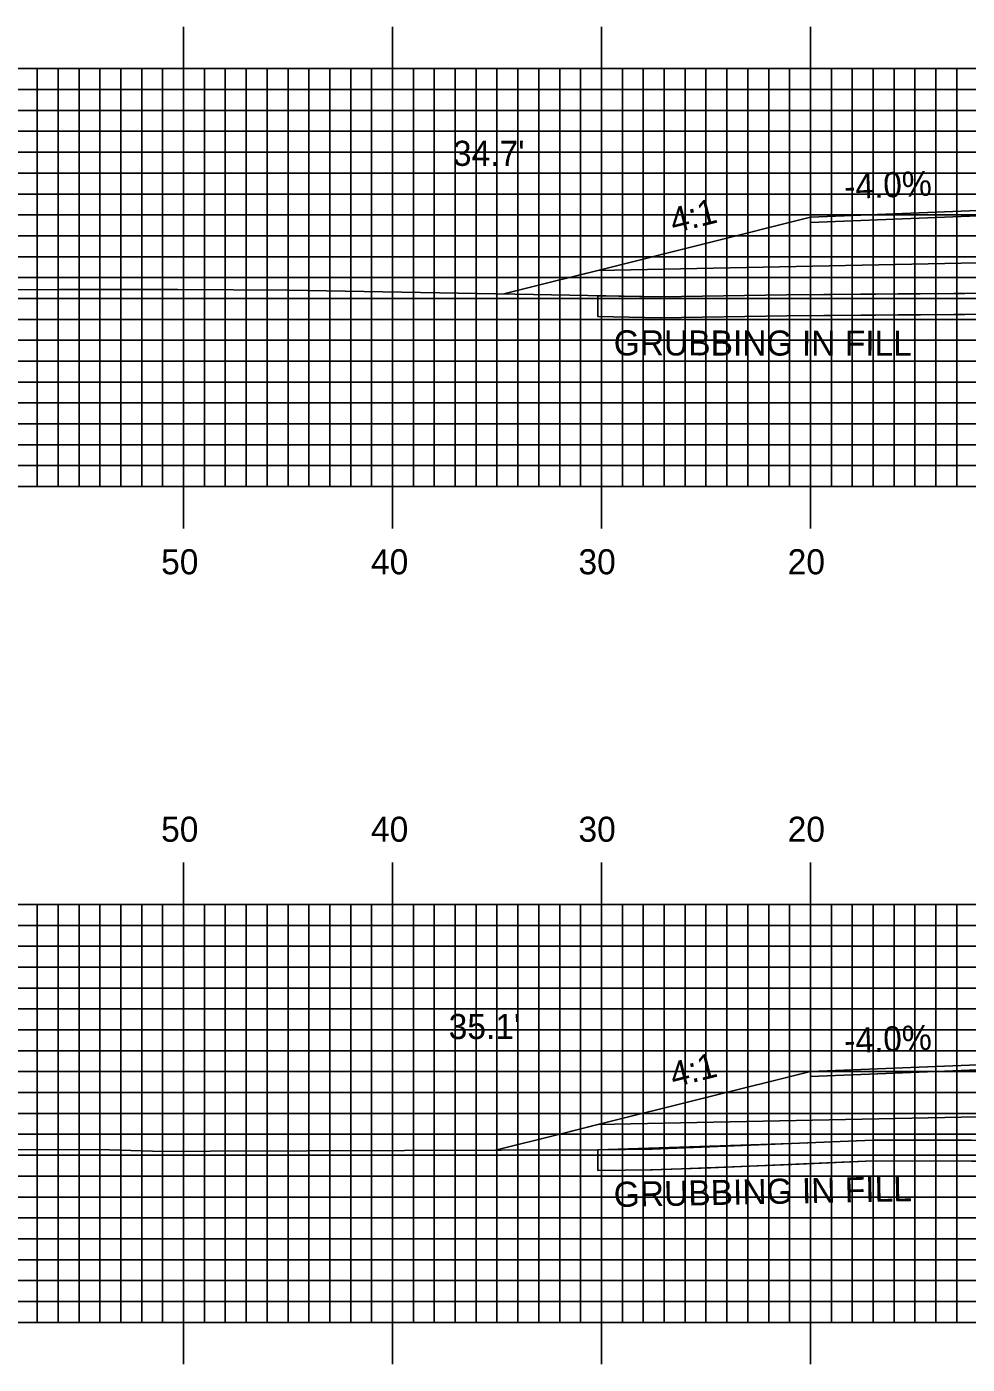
# Model space of a CAD drawing. Extents: x 1778712 to 1779055, y 442591 to 442811.
# Drawn here: x 1778820.3 to 1778865.3, y 442686.7 to 442750.7 of the extents above; entities that cross this region are included whole.
import ezdxf

# ---------------------------------------------------------------- set-up
doc = ezdxf.new("R2010")
doc.units = 0
for name, color, linetype in [('ANNOTATION', 7, 'Continuous'), ('D_Roadway_Centerline', 7, 'Continuous'), ('D_Roadway_Edge_Shoulder', 7, 'Continuous'), ('D_Roadway_SlopeLines', 7, 'Continuous'), ('D_Roadway_SubGrade', 7, 'Continuous'), ('D_Text_Standard', 7, 'Continuous'), ('GRUBBING IN FILL', 7, 'Continuous'), ('H_V ANNOTATION', 7, 'Continuous'), ('MAJOR', 7, 'Continuous'), ('MINOR', 7, 'Continuous'), ('S_Roadway_Centerline', 7, 'Continuous')]:
    doc.layers.add(name, color=color, linetype=linetype)

msp = doc.modelspace()

# ---------------------------------------------------------------- linework, layer by layer
at = {"layer": 'D_Roadway_Centerline'}
for points in [[(1778843.141, 442737.884), (1778845.246, 442738.41), (1778845.816, 442738.552), (1778846.159, 442738.638), (1778847.642, 442739.009), (1778857.816, 442741.552), (1778860.631, 442741.665), (1778865.816, 442741.872), (1778871.523, 442741.986), (1778877.816, 442742.112), (1778889.816, 442741.872), (1778909.797, 442741.073)], [(1778842.737, 442696.908), (1778845.816, 442697.677), (1778847.142, 442698.009), (1778847.643, 442698.134), (1778857.816, 442700.677), (1778865.816, 442700.997), (1778866.485, 442701.011), (1778877.816, 442701.237), (1778882.23, 442701.149), (1778889.816, 442700.997), (1778896.708, 442700.722), (1778908.134, 442700.264), (1778917.409, 442697.946)]]:
    msp.add_lwpolyline(points, dxfattribs=at)
at = {"layer": 'D_Roadway_Edge_Shoulder'}
for points in [[(1778865.816, 442741.872), (1778857.816, 442741.552), (1778857.816, 442741.302), (1778865.816, 442741.622)], [(1778865.816, 442700.997), (1778857.816, 442700.677), (1778857.816, 442700.427), (1778865.816, 442700.747)]]:
    msp.add_lwpolyline(points, close=True, dxfattribs=at)
at = {"layer": 'D_Roadway_SlopeLines'}
for points in [[(1778857.816, 442741.552), (1778847.642, 442739.009), (1778845.816, 442738.552), (1778843.141, 442737.884)], [(1778857.816, 442700.677), (1778847.643, 442698.134), (1778845.816, 442697.677), (1778842.737, 442696.908)]]:
    msp.add_lwpolyline(points, dxfattribs=at)
at = {"layer": 'D_Roadway_SubGrade'}
for points in [[(1778865.816, 442739.372), (1778847.642, 442739.009), (1778857.816, 442741.552), (1778857.816, 442741.302), (1778865.816, 442741.622), (1778877.816, 442741.862), (1778889.816, 442741.622), (1778909.797, 442740.823), (1778909.797, 442741.073), (1778918.927, 442738.791), (1778889.816, 442739.372), (1778877.816, 442739.612)], [(1778865.816, 442698.497), (1778847.643, 442698.134), (1778857.816, 442700.677), (1778857.816, 442700.427), (1778865.816, 442700.747), (1778877.816, 442700.987), (1778889.816, 442700.747), (1778908.134, 442700.014), (1778908.134, 442700.264), (1778917.409, 442697.946), (1778889.816, 442698.497), (1778877.816, 442698.737)]]:
    msp.add_lwpolyline(points, close=True, dxfattribs=at)
at = {"layer": 'GRUBBING IN FILL'}
for p, q in [((1778847.642, 442737.799), (1778847.642, 442736.798)), ((1778847.642, 442737.799), (1778847.642, 442736.798)), ((1778847.643, 442696.928), (1778847.643, 442695.928)), ((1778847.643, 442696.928), (1778847.643, 442695.928))]:
    msp.add_line(p, q, dxfattribs=at)
for points in [[(1778847.642, 442737.799), (1778850.644, 442737.739), (1778856.664, 442737.842), (1778862.003, 442737.881), (1778867.341, 442737.92), (1778870.689, 442737.882), (1778874.037, 442737.843), (1778877.816, 442737.91), (1778877.816, 442736.91), (1778874.04, 442736.843), (1778870.69, 442736.882), (1778867.339, 442736.92), (1778862.008, 442736.881), (1778856.676, 442736.842), (1778850.643, 442736.739), (1778847.642, 442736.798)], [(1778847.642, 442737.799), (1778850.644, 442737.739), (1778856.664, 442737.842), (1778862.003, 442737.881), (1778867.341, 442737.92), (1778870.689, 442737.882), (1778874.037, 442737.843), (1778877.816, 442737.91), (1778877.816, 442736.91), (1778874.04, 442736.843), (1778870.69, 442736.882), (1778867.339, 442736.92), (1778862.008, 442736.881), (1778856.676, 442736.842), (1778850.643, 442736.739), (1778847.642, 442736.798)], [(1778847.643, 442695.928), (1778847.643, 442696.928), (1778856.901, 442697.228), (1778860.796, 442697.389), (1778865.513, 442697.382), (1778873.154, 442697.34), (1778876.078, 442697.307), (1778877.816, 442697.339), (1778877.816, 442696.339), (1778876.081, 442696.307), (1778870.223, 442696.374), (1778865.52, 442696.382), (1778860.816, 442696.389), (1778856.93, 442696.228), (1778851.651, 442696.014), (1778850.184, 442695.961), (1778848.95, 442695.945)], [(1778847.643, 442695.928), (1778847.643, 442696.928), (1778856.901, 442697.228), (1778860.796, 442697.389), (1778865.513, 442697.382), (1778873.154, 442697.34), (1778876.078, 442697.307), (1778877.816, 442697.339), (1778877.816, 442696.339), (1778876.081, 442696.307), (1778870.223, 442696.374), (1778865.52, 442696.382), (1778860.816, 442696.389), (1778856.93, 442696.228), (1778851.651, 442696.014), (1778850.184, 442695.961), (1778848.95, 442695.945)]]:
    msp.add_lwpolyline(points, close=True, dxfattribs=at)
for points in [[(1778847.642, 442736.798), (1778850.643, 442736.739), (1778856.676, 442736.842), (1778867.339, 442736.92), (1778874.04, 442736.843), (1778881.679, 442736.978), (1778889.086, 442737.075), (1778903.647, 442737.274), (1778907.989, 442737.356)], [(1778847.642, 442736.798), (1778850.643, 442736.739), (1778856.676, 442736.842), (1778867.339, 442736.92), (1778874.04, 442736.843), (1778881.679, 442736.978), (1778889.086, 442737.075), (1778903.647, 442737.274), (1778907.989, 442737.356)], [(1778847.643, 442695.928), (1778850.258, 442695.962), (1778853.045, 442696.067), (1778860.816, 442696.389), (1778870.223, 442696.374), (1778876.081, 442696.307), (1778891.645, 442696.6), (1778900.58, 442696.804), (1778907.99, 442696.666)], [(1778847.643, 442695.928), (1778850.258, 442695.962), (1778853.045, 442696.067), (1778860.816, 442696.389), (1778870.223, 442696.374), (1778876.081, 442696.307), (1778891.645, 442696.6), (1778900.58, 442696.804), (1778907.99, 442696.666)]]:
    msp.add_lwpolyline(points, dxfattribs=at)
at = {"layer": 'MAJOR'}
for p, q in [((1778827.816, 442750.669), (1778827.816, 442748.665)), ((1778837.816, 442750.669), (1778837.816, 442748.665)), ((1778847.816, 442750.669), (1778847.816, 442748.665)), ((1778857.816, 442750.669), (1778857.816, 442748.665)), ((1778737.816, 442748.665), (1779017.816, 442748.665)), ((1778737.816, 442748.665), (1779017.816, 442748.665)), ((1778827.816, 442728.665), (1778827.816, 442748.665)), ((1778837.816, 442728.665), (1778837.816, 442748.665)), ((1778847.816, 442728.665), (1778847.816, 442748.665)), ((1778857.816, 442728.665), (1778857.816, 442748.665)), ((1778737.816, 442743.665), (1779017.816, 442743.665)), ((1778737.816, 442738.665), (1779017.816, 442738.665)), ((1778737.816, 442733.665), (1779017.816, 442733.665)), ((1778737.816, 442728.665), (1779017.816, 442728.665)), ((1778737.816, 442728.665), (1779017.816, 442728.665)), ((1778827.816, 442726.661), (1778827.816, 442728.665)), ((1778837.816, 442726.661), (1778837.816, 442728.665)), ((1778847.816, 442726.661), (1778847.816, 442728.665)), ((1778857.816, 442726.661), (1778857.816, 442728.665)), ((1778827.816, 442710.669), (1778827.816, 442708.665)), ((1778837.816, 442710.669), (1778837.816, 442708.665)), ((1778847.816, 442710.669), (1778847.816, 442708.665)), ((1778857.816, 442710.669), (1778857.816, 442708.665)), ((1778737.816, 442708.665), (1779017.816, 442708.665)), ((1778737.816, 442708.665), (1779017.816, 442708.665)), ((1778827.816, 442688.665), (1778827.816, 442708.665)), ((1778837.816, 442688.665), (1778837.816, 442708.665)), ((1778847.816, 442688.665), (1778847.816, 442708.665)), ((1778857.816, 442688.665), (1778857.816, 442708.665)), ((1778737.816, 442703.665), (1779017.816, 442703.665)), ((1778737.816, 442698.665), (1779017.816, 442698.665)), ((1778737.816, 442693.665), (1779017.816, 442693.665)), ((1778737.816, 442688.665), (1779017.816, 442688.665)), ((1778737.816, 442688.665), (1779017.816, 442688.665)), ((1778827.816, 442686.661), (1778827.816, 442688.665)), ((1778837.816, 442686.661), (1778837.816, 442688.665)), ((1778847.816, 442686.661), (1778847.816, 442688.665)), ((1778857.816, 442686.661), (1778857.816, 442688.665))]:
    msp.add_line(p, q, dxfattribs=at)
at = {"layer": 'MINOR'}
for p, q in [((1778820.816, 442728.665), (1778820.816, 442748.665)), ((1778821.816, 442728.665), (1778821.816, 442748.665)), ((1778822.816, 442728.665), (1778822.816, 442748.665)), ((1778823.816, 442728.665), (1778823.816, 442748.665)), ((1778824.816, 442728.665), (1778824.816, 442748.665)), ((1778825.816, 442728.665), (1778825.816, 442748.665)), ((1778826.816, 442728.665), (1778826.816, 442748.665)), ((1778828.816, 442728.665), (1778828.816, 442748.665)), ((1778829.816, 442728.665), (1778829.816, 442748.665)), ((1778830.816, 442728.665), (1778830.816, 442748.665)), ((1778831.816, 442728.665), (1778831.816, 442748.665)), ((1778832.816, 442728.665), (1778832.816, 442748.665)), ((1778833.816, 442728.665), (1778833.816, 442748.665)), ((1778834.816, 442728.665), (1778834.816, 442748.665)), ((1778835.816, 442728.665), (1778835.816, 442748.665)), ((1778836.816, 442728.665), (1778836.816, 442748.665)), ((1778838.816, 442728.665), (1778838.816, 442748.665)), ((1778839.816, 442728.665), (1778839.816, 442748.665)), ((1778840.816, 442728.665), (1778840.816, 442748.665)), ((1778841.816, 442728.665), (1778841.816, 442748.665)), ((1778842.816, 442728.665), (1778842.816, 442748.665)), ((1778843.816, 442728.665), (1778843.816, 442748.665)), ((1778844.816, 442728.665), (1778844.816, 442748.665)), ((1778845.816, 442728.665), (1778845.816, 442748.665)), ((1778846.816, 442728.665), (1778846.816, 442748.665)), ((1778848.816, 442728.665), (1778848.816, 442748.665)), ((1778849.816, 442728.665), (1778849.816, 442748.665)), ((1778850.816, 442728.665), (1778850.816, 442748.665)), ((1778851.816, 442728.665), (1778851.816, 442748.665)), ((1778852.816, 442728.665), (1778852.816, 442748.665)), ((1778853.816, 442728.665), (1778853.816, 442748.665)), ((1778854.816, 442728.665), (1778854.816, 442748.665)), ((1778855.816, 442728.665), (1778855.816, 442748.665)), ((1778856.816, 442728.665), (1778856.816, 442748.665)), ((1778858.816, 442728.665), (1778858.816, 442748.665)), ((1778859.816, 442728.665), (1778859.816, 442748.665)), ((1778860.816, 442728.665), (1778860.816, 442748.665)), ((1778861.816, 442728.665), (1778861.816, 442748.665)), ((1778862.816, 442728.665), (1778862.816, 442748.665)), ((1778863.816, 442728.665), (1778863.816, 442748.665)), ((1778864.816, 442728.665), (1778864.816, 442748.665)), ((1778737.816, 442747.665), (1779017.816, 442747.665)), ((1778737.816, 442746.665), (1779017.816, 442746.665)), ((1778737.816, 442745.665), (1779017.816, 442745.665)), ((1778737.816, 442744.665), (1779017.816, 442744.665)), ((1778737.816, 442742.665), (1779017.816, 442742.665)), ((1778737.816, 442741.665), (1779017.816, 442741.665)), ((1778737.816, 442740.665), (1779017.816, 442740.665)), ((1778737.816, 442739.665), (1779017.816, 442739.665)), ((1778737.816, 442737.665), (1779017.816, 442737.665)), ((1778737.816, 442736.665), (1779017.816, 442736.665)), ((1778737.816, 442735.665), (1779017.816, 442735.665)), ((1778737.816, 442734.665), (1779017.816, 442734.665)), ((1778737.816, 442732.665), (1779017.816, 442732.665)), ((1778737.816, 442731.665), (1779017.816, 442731.665)), ((1778737.816, 442730.665), (1779017.816, 442730.665)), ((1778737.816, 442729.665), (1779017.816, 442729.665)), ((1778820.816, 442688.665), (1778820.816, 442708.665)), ((1778821.816, 442688.665), (1778821.816, 442708.665)), ((1778822.816, 442688.665), (1778822.816, 442708.665)), ((1778823.816, 442688.665), (1778823.816, 442708.665)), ((1778824.816, 442688.665), (1778824.816, 442708.665)), ((1778825.816, 442688.665), (1778825.816, 442708.665)), ((1778826.816, 442688.665), (1778826.816, 442708.665)), ((1778828.816, 442688.665), (1778828.816, 442708.665)), ((1778829.816, 442688.665), (1778829.816, 442708.665)), ((1778830.816, 442688.665), (1778830.816, 442708.665)), ((1778831.816, 442688.665), (1778831.816, 442708.665)), ((1778832.816, 442688.665), (1778832.816, 442708.665)), ((1778833.816, 442688.665), (1778833.816, 442708.665)), ((1778834.816, 442688.665), (1778834.816, 442708.665)), ((1778835.816, 442688.665), (1778835.816, 442708.665)), ((1778836.816, 442688.665), (1778836.816, 442708.665)), ((1778838.816, 442688.665), (1778838.816, 442708.665)), ((1778839.816, 442688.665), (1778839.816, 442708.665)), ((1778840.816, 442688.665), (1778840.816, 442708.665)), ((1778841.816, 442688.665), (1778841.816, 442708.665)), ((1778842.816, 442688.665), (1778842.816, 442708.665)), ((1778843.816, 442688.665), (1778843.816, 442708.665)), ((1778844.816, 442688.665), (1778844.816, 442708.665)), ((1778845.816, 442688.665), (1778845.816, 442708.665)), ((1778846.816, 442688.665), (1778846.816, 442708.665)), ((1778848.816, 442688.665), (1778848.816, 442708.665)), ((1778849.816, 442688.665), (1778849.816, 442708.665)), ((1778850.816, 442688.665), (1778850.816, 442708.665)), ((1778851.816, 442688.665), (1778851.816, 442708.665)), ((1778852.816, 442688.665), (1778852.816, 442708.665)), ((1778853.816, 442688.665), (1778853.816, 442708.665)), ((1778854.816, 442688.665), (1778854.816, 442708.665)), ((1778855.816, 442688.665), (1778855.816, 442708.665)), ((1778856.816, 442688.665), (1778856.816, 442708.665)), ((1778858.816, 442688.665), (1778858.816, 442708.665)), ((1778859.816, 442688.665), (1778859.816, 442708.665)), ((1778860.816, 442688.665), (1778860.816, 442708.665)), ((1778861.816, 442688.665), (1778861.816, 442708.665)), ((1778862.816, 442688.665), (1778862.816, 442708.665)), ((1778863.816, 442688.665), (1778863.816, 442708.665)), ((1778864.816, 442688.665), (1778864.816, 442708.665)), ((1778737.816, 442707.665), (1779017.816, 442707.665)), ((1778737.816, 442706.665), (1779017.816, 442706.665)), ((1778737.816, 442705.665), (1779017.816, 442705.665)), ((1778737.816, 442704.665), (1779017.816, 442704.665)), ((1778737.816, 442702.665), (1779017.816, 442702.665)), ((1778737.816, 442701.665), (1779017.816, 442701.665)), ((1778737.816, 442700.665), (1779017.816, 442700.665)), ((1778737.816, 442699.665), (1779017.816, 442699.665)), ((1778737.816, 442697.665), (1779017.816, 442697.665)), ((1778737.816, 442696.665), (1779017.816, 442696.665)), ((1778737.816, 442695.665), (1779017.816, 442695.665)), ((1778737.816, 442694.665), (1779017.816, 442694.665)), ((1778737.816, 442692.665), (1779017.816, 442692.665)), ((1778737.816, 442691.665), (1779017.816, 442691.665)), ((1778737.816, 442690.665), (1779017.816, 442690.665)), ((1778737.816, 442689.665), (1779017.816, 442689.665))]:
    msp.add_line(p, q, dxfattribs=at)
at = {"layer": 'S_Roadway_Centerline'}
for points in [[(1778815.817, 442738.05), (1778821.889, 442738.094), (1778827.538, 442738.091), (1778832.855, 442738.061), (1778844.563, 442737.86), (1778850.644, 442737.739), (1778856.664, 442737.842), (1778867.341, 442737.92), (1778874.037, 442737.843), (1778881.664, 442737.978), (1778889.073, 442738.075), (1778903.631, 442738.274), (1778909.074, 442738.377), (1778912.943, 442738.242), (1778929.396, 442738.238), (1778932.358, 442738.291)], [(1778737.816, 442696.093), (1778746.066, 442696.061), (1778756.188, 442696.432), (1778757.024, 442696.435), (1778779.083, 442696.346), (1778781.608, 442696.381), (1778801.369, 442696.642), (1778805.175, 442696.733), (1778814.744, 442696.936), (1778824.282, 442696.921), (1778826.844, 442696.839), (1778829.092, 442696.851), (1778847.692, 442696.929), (1778850.233, 442696.961), (1778853.005, 442697.067), (1778860.796, 442697.389), (1778870.23, 442697.374), (1778876.078, 442697.307), (1778891.625, 442697.599), (1778900.578, 442697.804), (1778919.12, 442697.461), (1778923.545, 442697.44), (1778930.541, 442697.551)]]:
    msp.add_lwpolyline(points, dxfattribs=at)

# ---------------------------------------------------------------- texts
at = {"layer": 'ANNOTATION'}
for s, rotation, p in [('-4.0%', 2.29073, (1778859.448, 442742.419)), ('4:1', 14.0329, (1778851.265, 442740.776)), ('-4.0%', 2.29053, (1778859.448, 442701.544)), ('4:1', 14.03477, (1778851.265, 442699.901))]:
    msp.add_text(s, height=1.2, rotation=rotation, dxfattribs=at).set_placement(p)
at = {"layer": 'D_Text_Standard'}
for s, p in [("34.7'", (1778840.706, 442744.011)), ("35.1'", (1778840.504, 442702.225))]:
    msp.add_text(s, height=1.2, dxfattribs=at).set_placement(p)
at = {"layer": 'GRUBBING IN FILL'}
for rotation, p in [(359.9351, (1778848.401, 442734.941)), (1.1335, (1778848.413, 442694.185))]:
    msp.add_text('GRUBBING IN FILL', height=1.2, rotation=rotation, dxfattribs=at).set_placement(p)
at = {"layer": 'H_V ANNOTATION'}
for s, p in [('50', (1778826.745, 442724.465)), ('40', (1778836.788, 442724.465)), ('30', (1778846.713, 442724.465)), ('20', (1778856.724, 442724.465)), ('50', (1778826.745, 442711.665)), ('40', (1778836.788, 442711.665)), ('30', (1778846.713, 442711.665)), ('20', (1778856.724, 442711.665))]:
    msp.add_text(s, height=1.2, dxfattribs=at).set_placement(p)

doc.saveas('drawing.dxf')
